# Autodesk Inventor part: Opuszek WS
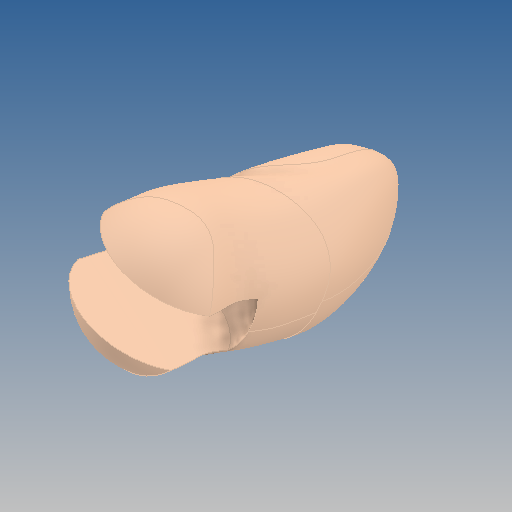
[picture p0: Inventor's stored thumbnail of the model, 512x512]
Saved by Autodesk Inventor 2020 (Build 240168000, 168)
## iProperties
Created: 2019-10
Part Number: Opuszek WS
Material: GFRP
Document SubType Name: Modeling
Designer: yello
Density: 1.75 g/cm^3
Appearance: Default
Author: yello
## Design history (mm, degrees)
feature "Opuszek WS"
body "Solid1"
